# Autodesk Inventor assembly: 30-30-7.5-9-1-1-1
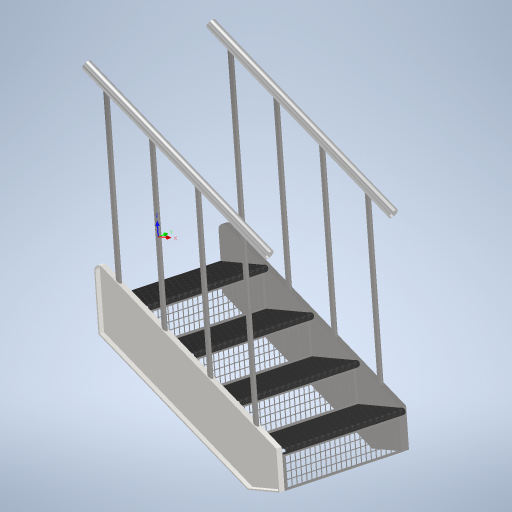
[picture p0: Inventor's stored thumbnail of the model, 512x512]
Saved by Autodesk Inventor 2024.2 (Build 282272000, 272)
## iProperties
RuleStatus: InUse
Company: Elevation Stair Company
Created: 2022-06
Part Number: 30-30-7.5-9-1-1-1
Document SubType Name: Assembly
Designer: David Reaume
Description: Metal Stairs
AfterAnyUserParamChange0: Type Name
Run: 10.000 in
TheAngle: 36.87 deg
TargetRise: 7.000 in
Rise: 7.500 in
Height: 30.000 in
Width: 36.000 in
StringerWidth: 12.000 in
StringerThickness: 1.500 in
StringerLength: 50.000 in
NumberOfSteps: 5.000 ul
Length: 40.000 in
TreadThickness: 1.250 in
StringerStockLength: 51.000 in
RailingStockLength: 50.000 in
RailingWidth: 3.000 in
RailingThickness: 2.000 in
RightRail: True
LeftRail: True
StringerMaterial: Steel, Mild, Welded
TreadMaterial: Steel, Wrought
RiserMaterial: Aluminum 6061
BalusterMaterial: Stainless Steel
HandrailMaterial: Aluminum 6061
HasHandrail: True
HasRiser: True
Type_Name: 30-36-7.5-10-1-1-1
BalusterLength: 36.000 in
BalusterDia: 1.000 in
Author: David Reaume
Run: 9.000 in
TheAngle: 39.81 deg
TargetRise: 7.250 in
Width: 30.000 in
StringerWidth: 10.000 in
StringerLength: 46.861 in
Length: 36.000 in
StringerStockLength: 48.000 in
RailingStockLength: 46.861 in
StringerMaterial: Steel, Galvanized
RiserMaterial: Steel, Galvanized
BalusterMaterial: Steel, Galvanized
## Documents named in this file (13)
- D:\Staircase Sample\Staircase Sample.iam
- D:\Staircase Sample\Stringer.ipt
- D:\Staircase Sample\Tread.ipt
- D:\Staircase Sample\Riser.ipt
- D:\Staircase Sample\Baluster.ipt
- D:\Staircase Sample\Railing.ipt
- D:\Staircase Sample\Left Stringer_MIR.ipt
- D:\MID Staircase\Stringer.ipt
- D:\MID Staircase\Tread.ipt
- D:\MID Staircase\Riser.ipt
- D:\MID Staircase\Baluster.ipt
- D:\MID Staircase\Railing.ipt
- D:\MID Staircase\Left Stringer_MIR.ipt
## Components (20 placed, 7 different names)
1. Stringer
2. Left Stringer_MIR:1
3. Right Railing
4. Left Railing — Flush:7, Flush:8, Flush:9
5. Tread:1
6. Tread:2
7. Tread:3
8. Tread:4
9. Riser:1
10. Riser:2
11. Riser:3
12. Riser:4
13. Baluster:1
14. Baluster:12
15. Baluster:15
16. Baluster:17
17. Baluster:7 — Flush:11, Flush:12
18. Baluster:8
19. Baluster:13
20. Baluster:16
## Component patterns: Tread Pattern (4 elements), Riser Pattern (4 elements), Right Baluster Pattern (4 elements), Left Baluster Pattern (4 elements)
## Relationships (5: Flush 5)
- Flush:7: Left Railing
- Flush:8: Left Railing
- Flush:9: Left Railing
- Flush:11: Baluster:7
- Flush:12: Baluster:7
## Named parameters: TheAngle = 6.94738 mm, StringerThickness = 38.1 mm, StringerLength = 1190.28205 mm, Length = 914.4 mm, TheAngleRounded = 6.94816 mm, StringerStockLength = 1219.2 mm, DiagonalTreadSpacing = 297.57051 mm, BalusterDia = 25.4 mm, BalusterLength = 914.4 mm, RailingStockLength = 1190.28205 mm, RailingWidth = 76.2 mm, RailingThickness = 50.8 mm, StringerSpacing = 876.3 mm
